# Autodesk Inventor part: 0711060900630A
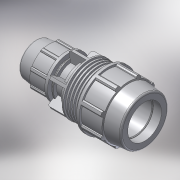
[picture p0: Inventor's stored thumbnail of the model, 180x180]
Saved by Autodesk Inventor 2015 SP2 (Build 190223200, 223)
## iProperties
Created: 2017-02
Part Number: 0711060900630A
Material: PVC-Piping
Description: PLASSON REDUCING COUPLER 90-63
Document SubType Name: Modeling
Designer: KIM
Mass: 92.6774 g
Surface Area: 199.44 cm^2
Volume: 66.1981 cm^3
Density: 1.4 g/cm^3
Appearance: Smooth - White
Author: KIM
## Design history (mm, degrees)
derived "87110.ipt"
feature "Solid1::87110.ipt"
tag "TaggingFeature1"
body "Solid1"
other parameters: "d4" = 24.33333, "d5" = 41.71429, "d7" = 154, "d9" = 41.71429, "d11" = 4.17143, "d12" = 123.2, "d13" = 120 deg, "d14" = 126, "d15" = 6 deg, "d16" = 138.6, "d18" = 4.5, "d19" = 35 deg, "d20" = 17.5 deg, "d21" = 143.22, "d23" = 0, "d25" = 360 deg, "d27" = 3.08, "d42" = 64.24, "d46" = 1.8, "d51" = 292, "d52" = 41.71429, "d53" = 8 deg, "d56" = 88.2, "d57" = 63, "d58" = 81, "d59" = 56.7, "d60" = 101.7, "d61" = 90.4, "d62" = 36.5, "d63" = 52.56, "d64" = 120 deg, "d65" = 113, "d68" = 20.85714, "d74" = 105.09, "d75" = 35 deg, "d76" = 17.5 deg, "d78" = 0, "d80" = 360 deg, "d85" = 2.26, "d88" = 1.26, "d93" = 115, "d94" = 107.8, "d98" = 7.53333, "d99" = 0, "d100" = 6.16, "d102" = 360 deg, "d104" = 2, "d106" = 0, "d107" = 7.53333, "d108" = 0, "d109" = 7.53333, "d110" = 0, "d111" = 3.41667, "d112" = 3.41667, "d113" = 3.41667, "d114" = 4.25171, "d116" = 4.25171, "d119" = 8.50343, "d125" = 135.828, "E_" = 154, "H_" = 292, "d_1" = 63, "E_1" = 113, "l_1" = 115, "d96" = 10.25, "d115" = 42.51714
